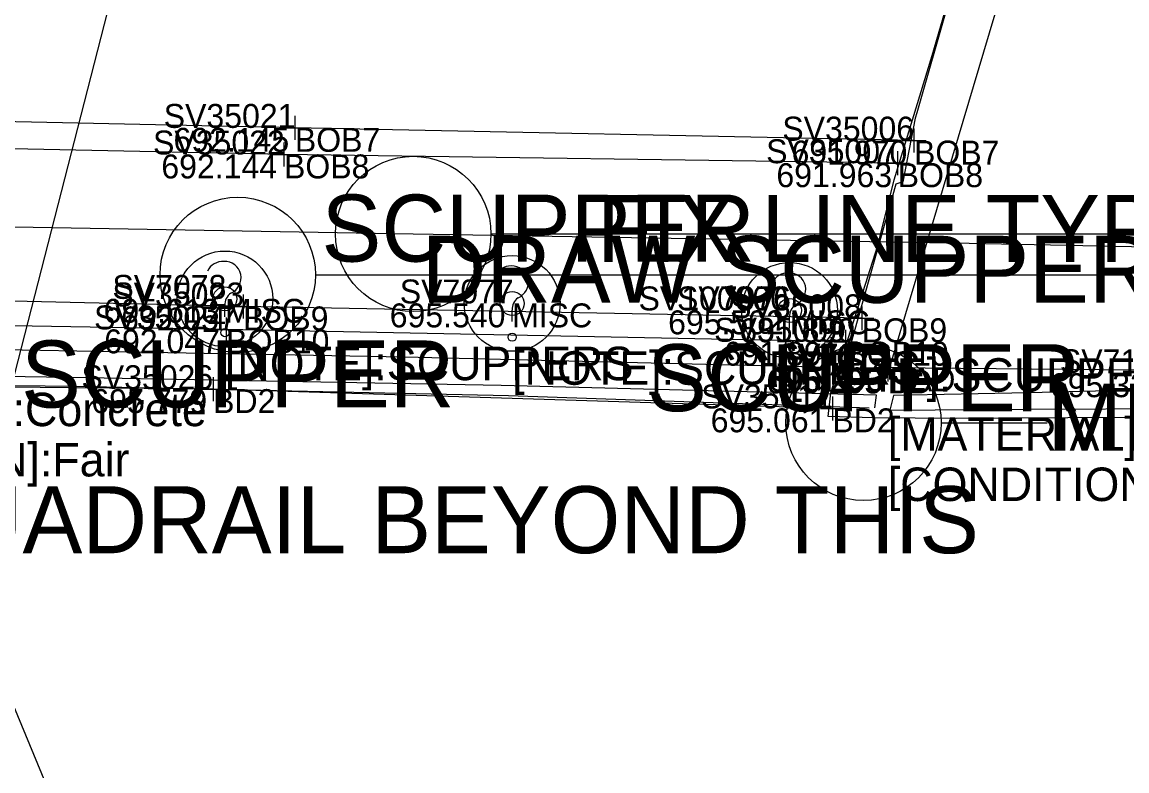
# Model space of a CAD drawing. Extents: x 1659932 to 1663108, y 619867 to 620611.
# Drawn here: x 1661479.69 to 1661525.83, y 620195.14 to 620226.44 of the extents above; entities that cross this region are included whole.
import ezdxf

# ---------------------------------------------------------------- set-up
doc = ezdxf.new("R2010")
doc.units = 0
for name, color, linetype in [('BR_X_Rail_Object', 7, 'Continuous'), ('BR_X_SV_Abut', 7, 'Continuous'), ('BR_X_SV_Bottom_of_Beam', 7, 'Continuous'), ('BR_X_SV_Bottom_of_Beam_Text', 7, 'Continuous'), ('BR_X_SV_Deck_Top', 7, 'Continuous'), ('BR_X_SV_Deck_Top_Text', 7, 'Continuous'), ('PM_X_Edge_Line', 7, 'Continuous'), ('RD_X_Concrete_Pad', 7, 'Continuous'), ('RD_X_Misc_Items', 7, 'Continuous'), ('RD_X_Text', 7, 'Continuous'), ('SC_Scratch6', 7, 'Continuous'), ('SV_X_Break_Lines', 7, 'Continuous'), ('SV_X_Shot_Marker', 7, 'Continuous'), ('SV_X_Text', 7, 'Continuous'), ('SV_X_Text_Comment', 7, 'Continuous'), ('SV_X_Text_Elevation', 7, 'Continuous'), ('SV_X_Text_Name', 7, 'Continuous'), ('SV_X_Toe_of_Slope', 7, 'Continuous')]:
    doc.layers.add(name, color=color, linetype=linetype)

msp = doc.modelspace()

# ---------------------------------------------------------------- linework, layer by layer
at = {"layer": 'BR_X_Rail_Object'}
for points in [[(1661515.301, 620210.312), (1661515.369, 620210.843), (1661499.689, 620211.245), (1661481.611, 620211.584), (1661464.483, 620211.85), (1661450.154, 620212.164), (1661434.35, 620212.457)], [(1661433.513, 620212.015), (1661450.818, 620211.691), (1661464.185, 620211.422), (1661481.921, 620211.226), (1661499.995, 620210.831), (1661515.07, 620210.323)], [(1661529.626, 620210.842), (1661528.41, 620211.108), (1661521.735, 620210.949), (1661516.075, 620210.839), (1661515.935, 620210.216), (1661521.627, 620210.268), (1661528.262, 620210.294), (1661529.835, 620210.32), (1661529.865, 620210.732)]]:
    msp.add_lwpolyline(points, dxfattribs=at)
at = {"layer": 'BR_X_SV_Abut'}
msp.add_lwpolyline([(1661523.782, 620245.548), (1661521.437, 620237.652), (1661521.38, 620237.412), (1661519.237, 620230.239), (1661519.158, 620229.96), (1661518.402, 620227.366), (1661518.318, 620227.072), (1661517.057, 620222.643), (1661516.991, 620222.429), (1661516.471, 620219.763), (1661516.177, 620219.661), (1661513.803, 620211.222)], dxfattribs=at)
at = {"layer": 'BR_X_SV_Bottom_of_Beam'}
for points in [[(1661516.938, 620221.488), (1661491.079, 620222.019), (1661465.187, 620222.58), (1661439.251, 620223.092), (1661413.441, 620223.61), (1661387.584, 620224.174), (1661361.703, 620224.657), (1661335.742, 620225.126), (1661309.876, 620225.693), (1661284.015, 620226.238), (1661258.155, 620226.696), (1661232.1, 620227.235)], [(1661516.255, 620220.542), (1661490.624, 620220.907), (1661464.53, 620221.454), (1661438.64, 620222.101), (1661412.707, 620222.613), (1661386.76, 620223.066), (1661360.949, 620223.557), (1661335.05, 620224.176), (1661309.206, 620224.717), (1661283.267, 620225.126), (1661257.537, 620225.694), (1661231.605, 620226.262)], [(1661514.756, 620214.059), (1661488.914, 620214.555), (1661463.017, 620215.148), (1661437.126, 620215.616), (1661411.256, 620216.167), (1661385.428, 620216.691), (1661359.541, 620217.184), (1661333.602, 620217.682), (1661307.754, 620218.183), (1661281.891, 620218.773), (1661255.858, 620219.275), (1661229.67, 620219.799)], [(1661514.073, 620213.08), (1661488.21, 620213.597), (1661462.263, 620214.044), (1661436.515, 620214.643), (1661410.516, 620215.165), (1661384.602, 620215.601), (1661358.815, 620216.084), (1661332.968, 620216.701), (1661307.113, 620217.251), (1661281.101, 620217.691), (1661255.319, 620218.266), (1661229.464, 620218.851)]]:
    msp.add_lwpolyline(points, dxfattribs=at)
at = {"layer": 'BR_X_SV_Deck_Top'}
msp.add_lwpolyline([(1661513.529, 620210.295), (1661487.664, 620211.099), (1661461.66, 620211.354), (1661435.632, 620211.885), (1661409.962, 620212.424), (1661383.838, 620212.928), (1661332.298, 620213.947), (1661306.248, 620214.439), (1661280.429, 620214.969), (1661254.732, 620215.771)], dxfattribs=at)
at = {"layer": 'PM_X_Edge_Line'}
msp.add_lwpolyline([(1661202.201, 620223.591), (1661213.111, 620223.268), (1661228.394, 620222.766), (1661259.553, 620221.998), (1661275.152, 620221.639), (1661292.516, 620221.273), (1661314.563, 620220.783), (1661337.968, 620220.356), (1661364.828, 620219.904), (1661379.245, 620219.635), (1661405.952, 620219.205), (1661427.476, 620218.875), (1661447.989, 620218.475), (1661471.403, 620218.024), (1661496.022, 620217.585), (1661519.238, 620217.199), (1661540.284, 620216.766), (1661543.975, 620216.723)], dxfattribs=at)
at = {"layer": 'RD_X_Concrete_Pad'}
msp.add_lwpolyline([(1661551.786, 620244.408), (1661525.769, 620245.111), (1661515.918, 620212.007), (1661542.622, 620211.759)], close=True, dxfattribs=at)
at = {"layer": 'RD_X_Misc_Items'}
for p, q in [((1661488.157, 620214.118), (1661488.157, 620214.593)), ((1661500.155, 620213.927), (1661500.155, 620214.402)), ((1661511.742, 620213.636), (1661511.742, 620214.111)), ((1661511.742, 620213.636), (1661511.742, 620214.111))]:
    msp.add_line(p, q, dxfattribs=at)
for centre, radius in [((1661488.157, 620214.873), 2), ((1661500.155, 620214.682), 2), ((1661511.742, 620214.391), 2), ((1661511.742, 620214.391), 2), ((1661488.157, 620214.873), 0.5), ((1661488.157, 620214.873), 0.5), ((1661500.155, 620214.682), 0.5), ((1661500.155, 620214.682), 0.5), ((1661511.742, 620214.391), 0.5), ((1661511.742, 620214.391), 0.5), ((1661488.157, 620213.461), 0.17), ((1661500.155, 620213.27), 0.17), ((1661511.742, 620212.979), 0.17), ((1661511.742, 620212.979), 0.17)]:
    msp.add_circle(centre, radius, dxfattribs=at)
for centre, radius, start, end in [((1661488.093, 620215.684), 0.754, 88.324, 152.5385), ((1661488.145, 620215.751), 0.688, 291.9329, 92.4584), ((1661500.091, 620215.493), 0.754, 88.324, 152.5385), ((1661500.143, 620215.56), 0.688, 291.9329, 92.4584), ((1661511.678, 620215.202), 0.754, 88.324, 152.5385), ((1661511.678, 620215.202), 0.754, 88.324, 152.5385), ((1661511.73, 620215.269), 0.688, 291.9329, 92.4584), ((1661511.73, 620215.269), 0.688, 291.9329, 92.4584), ((1661488.743, 620214.635), 0.587, 125.4618, 184.0829), ((1661500.741, 620214.444), 0.587, 125.4618, 184.0829), ((1661512.328, 620214.153), 0.587, 125.4618, 184.0829), ((1661512.328, 620214.153), 0.587, 125.4618, 184.0829)]:
    msp.add_arc(centre, radius, start, end, dxfattribs=at)
at = {"layer": 'SC_Scratch6'}
for p, q in [((1661499.267, 620217.585), (1661532.07, 620217.585)), ((1661491.937, 620215.875), (1661525.891, 620215.875)), ((1661518.072, 620209.689), (1661522.501, 620209.689))]:
    msp.add_line(p, q, dxfattribs=at)
for centre in [(1661496.022, 620217.585), (1661488.692, 620215.875), (1661514.827, 620209.689)]:
    msp.add_circle(centre, 3.245, dxfattribs=at)
at = {"layer": 'SV_X_Break_Lines'}
for points in [[(1661513.46, 620210.943), (1661515.433, 620217.103), (1661516.114, 620219.841), (1661517.694, 620225.043), (1661519.67, 620231.823), (1661520.681, 620235.317), (1661521.758, 620239.035), (1661522.407, 620241.298), (1661523.021, 620243.437), (1661523.887, 620246.392)], [(1661228.67, 620217.714), (1661237.329, 620217.546), (1661248.531, 620217.329), (1661262.126, 620217.116), (1661283.4, 620216.641), (1661303.8, 620216.137), (1661335.243, 620215.455), (1661384.24, 620214.497), (1661403.674, 620214.086), (1661434.655, 620213.563), (1661466.755, 620212.973), (1661495.661, 620212.446), (1661513.396, 620212.012)], [(1661530.305, 620211.217), (1661530.225, 620209.901), (1661526.586, 620209.92), (1661523.365, 620209.905), (1661518.724, 620209.869), (1661515.249, 620209.895), (1661513.359, 620209.953), (1661513.46, 620210.943)]]:
    msp.add_lwpolyline(points, dxfattribs=at)
at = {"layer": 'SV_X_Shot_Marker'}
for p, q in [((1661491.079, 620222.519), (1661491.079, 620221.519)), ((1661490.579, 620222.019), (1661491.579, 620222.019)), ((1661491.079, 620222.019), (1661491.079, 620222.019)), ((1661516.938, 620221.988), (1661516.938, 620220.988)), ((1661516.438, 620221.488), (1661517.438, 620221.488)), ((1661516.938, 620221.488), (1661516.938, 620221.488)), ((1661490.624, 620221.407), (1661490.624, 620220.407)), ((1661516.255, 620221.042), (1661516.255, 620220.042)), ((1661490.124, 620220.907), (1661491.124, 620220.907)), ((1661490.624, 620220.907), (1661490.624, 620220.907)), ((1661515.755, 620220.542), (1661516.755, 620220.542)), ((1661516.255, 620220.542), (1661516.255, 620220.542)), ((1661488.914, 620215.055), (1661488.914, 620214.055)), ((1661488.414, 620214.555), (1661489.414, 620214.555)), ((1661488.914, 620214.555), (1661488.914, 620214.555)), ((1661514.756, 620214.559), (1661514.756, 620213.559)), ((1661488.21, 620214.097), (1661488.21, 620213.097)), ((1661514.256, 620214.059), (1661515.256, 620214.059)), ((1661514.756, 620214.059), (1661514.756, 620214.059)), ((1661487.71, 620213.597), (1661488.71, 620213.597)), ((1661488.21, 620213.597), (1661488.21, 620213.597)), ((1661514.073, 620213.58), (1661514.073, 620212.58)), ((1661513.573, 620213.08), (1661514.573, 620213.08)), ((1661514.073, 620213.08), (1661514.073, 620213.08)), ((1661515.842, 620212.422), (1661515.842, 620211.422)), ((1661515.918, 620212.507), (1661515.918, 620211.507)), ((1661515.342, 620211.922), (1661516.342, 620211.922)), ((1661515.418, 620212.007), (1661516.418, 620212.007)), ((1661515.842, 620211.922), (1661515.842, 620211.922)), ((1661515.918, 620212.007), (1661515.918, 620212.007)), ((1661487.664, 620211.599), (1661487.664, 620210.599)), ((1661487.164, 620211.099), (1661488.164, 620211.099)), ((1661487.664, 620211.099), (1661487.664, 620211.099)), ((1661513.529, 620210.795), (1661513.529, 620209.795)), ((1661513.029, 620210.295), (1661514.029, 620210.295)), ((1661513.529, 620210.295), (1661513.529, 620210.295))]:
    msp.add_line(p, q, dxfattribs=at)
at = {"layer": 'SV_X_Toe_of_Slope'}
msp.add_lwpolyline([(1661490.605, 620170.614), (1661477.149, 620203.096), (1661498.786, 620287.484), (1661510.242, 620298.378), (1661539.687, 620302.32)], dxfattribs=at)

# ---------------------------------------------------------------- texts
at = {"layer": 'BR_X_SV_Bottom_of_Beam_Text'}
for s, p in [('SV35021', (1661485.601, 620222.019)), ('SV35006', (1661511.438, 620221.488)), ('SV35022', (1661485.155, 620220.907)), ('692.145', (1661486.009, 620221.019)), ('BOB7', (1661491.079, 620221.019)), ('SV35007', (1661510.763, 620220.542)), ('691.970', (1661511.824, 620220.488)), ('BOB7', (1661516.938, 620220.488)), ('692.144', (1661485.502, 620219.907)), ('BOB8', (1661490.624, 620219.907)), ('691.963', (1661511.191, 620219.542)), ('BOB8', (1661516.255, 620219.542)), ('SV35023', (1661483.454, 620214.555)), ('SV35008', (1661509.259, 620214.059)), ('SV35024', (1661482.692, 620213.597)), ('692.057', (1661483.818, 620213.555)), ('BOB9', (1661488.914, 620213.555)), ('SV35009', (1661508.593, 620213.08)), ('691.890', (1661509.642, 620213.059)), ('BOB9', (1661514.756, 620213.059)), ('692.047', (1661483.114, 620212.597)), ('BOB10', (1661488.21, 620212.597)), ('691.891', (1661508.991, 620212.08)), ('BOB10', (1661514.073, 620212.08))]:
    msp.add_text(s, height=1, dxfattribs=at).set_placement(p)
at = {"layer": 'BR_X_SV_Deck_Top_Text'}
for s, p in [('SV7072', (1661511.171, 620211.922)), ('SV35026', (1661482.164, 620211.099)), ('695.295', (1661510.772, 620210.922)), ('BD', (1661515.842, 620210.922)), ('SV35011', (1661508.051, 620210.295)), ('695.779', (1661482.58, 620210.099)), ('BD2', (1661487.664, 620210.099)), ('695.061', (1661508.447, 620209.295)), ('BD2', (1661513.529, 620209.295))]:
    msp.add_text(s, height=1, dxfattribs=at).set_placement(p)
at = {"layer": 'RD_X_Text'}
for p in [(1661492.192, 620216.43), (1661479.644, 620210.333), (1661505.792, 620210.177)]:
    msp.add_text('SCUPPER', height=2.8, dxfattribs=at).set_placement(p)
at = {"layer": 'SC_Scratch6'}
for s, p in [('FIX LINE TYPES', (1661503.696, 620216.419)), ('DRAW SCUPPER', (1661496.367, 620214.708)), ('MISSING BREAK LINES', (1661522.501, 620208.522)), ('MISSING GUADRAIL BEYOND THIS', (1661457.236, 620204.242))]:
    msp.add_text(s, height=2.79999, dxfattribs=at).set_placement(p)
at = {"layer": 'SV_X_Text'}
for s, p in [('[NOTE]:SCUPPERS', (1661488.157, 620211.473)), ('[NOTE]:SCUPPERS', (1661500.155, 620211.282)), ('[NOTE]:SCUPPERS', (1661511.742, 620210.991)), ('[NOTE]:SCUPPERS', (1661511.742, 620210.991)), ('[MATERIAL]:Concrete', (1661468.881, 620209.552)), ('[MATERIAL]:Concrete', (1661515.842, 620208.522)), ('[CONDITION]:Fair', (1661468.881, 620207.452)), ('[CONDITION]:Fair', (1661515.842, 620206.422))]:
    msp.add_text(s, height=1.4, dxfattribs=at).set_placement(p)
at = {"layer": 'SV_X_Text_Comment'}
for s, p in [('MISC', (1661488.157, 620213.873)), ('MISC', (1661500.155, 620213.682)), ('MISC', (1661511.742, 620213.391)), ('MISC', (1661511.742, 620213.391)), ('PAD', (1661515.918, 620211.007))]:
    msp.add_text(s, height=1, dxfattribs=at).set_placement(p)
at = {"layer": 'SV_X_Text_Elevation'}
for s, p in [('695.613', (1661483.093, 620213.873)), ('695.540', (1661495.041, 620213.682)), ('695.502', (1661506.669, 620213.391)), ('695.502', (1661506.669, 620213.391)), ('695.293', (1661510.854, 620211.007)), ('695.337', (1661522.617, 620210.763))]:
    msp.add_text(s, height=1, dxfattribs=at).set_placement(p)
at = {"layer": 'SV_X_Text_Name'}
for s, p in [('SV7078', (1661483.458, 620214.873)), ('SV7077', (1661495.461, 620214.682)), ('SV100000', (1661505.434, 620214.391)), ('SV7076', (1661507.04, 620214.391)), ('SV7073', (1661511.256, 620212.007)), ('SV7111', (1661523.033, 620211.763))]:
    msp.add_text(s, height=1, dxfattribs=at).set_placement(p)

doc.saveas('drawing.dxf')
